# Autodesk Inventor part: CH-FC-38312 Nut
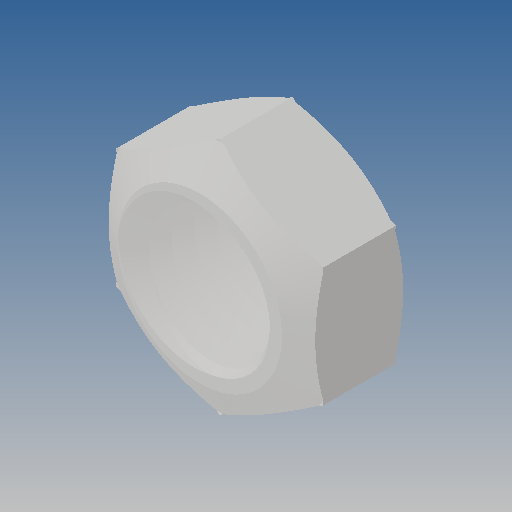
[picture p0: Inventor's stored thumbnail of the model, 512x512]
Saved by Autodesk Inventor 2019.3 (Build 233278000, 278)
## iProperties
Created: 2012-09
Part Number: CH-FC-38312 Nut
Material: Ogólny
Document SubType Name: Modeling
Designer: CADENGINEERING4
Density: 1 g/cm^3
Appearance: Domyślna
Author: CADENGINEERING4
Revision Number: ÈÎºÎ
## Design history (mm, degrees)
feature "ÇÐ³ý-É¨Ãè1"
node "Bryła1"
